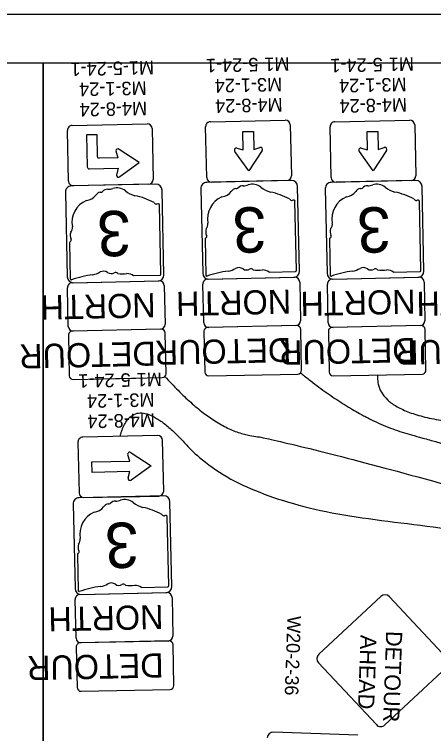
# Model space of a CAD drawing. Extents: x -15.3 to 34, y 0 to 22.
# Drawn here: x 1.2 to 5.53, y 14.57 to 22 of the extents above; entities that cross this region are included whole.
import ezdxf

# ---------------------------------------------------------------- set-up
doc = ezdxf.new("R2010")
doc.units = 0
for name, color, linetype in [('SC_Scratch1', 7, 'Continuous'), ('SH_Border', 7, 'Continuous'), ('SH_Cut_Line', 7, 'Continuous'), ('SH_Text', 7, 'Continuous'), ('SN_P_Signs', 7, 'Continuous')]:
    doc.layers.add(name, color=color, linetype=linetype)

msp = doc.modelspace()

# ---------------------------------------------------------------- linework, layer by layer
at = {"layer": 'SH_Border'}
for points in [[(0.5, 21.5), (1.5, 21.5), (1.5, 0.5), (0.5, 0.5)], [(1.5, 21.5), (33.5, 21.5), (33.5, 0.5), (1.5, 0.5)]]:
    msp.add_lwpolyline(points, close=True, dxfattribs=at)
at = {"layer": 'SH_Cut_Line'}
msp.add_lwpolyline([(0, 0), (34, 0), (34, 22), (0, 22)], close=True, dxfattribs=at)
at = {"layer": 'SH_Text'}
for points in [[(4.1592, 18.2966), (4.7515, 17.8162), (5.7312, 17.533), (8.5118, 16.773), (8.9677, 16.9331), (8.973, 16.8191)], [(2.759, 18.259), (3.2529, 17.7067), (4.0517, 17.5875), (7.8335, 16.5399), (8.7455, 16.2122), (8.9206, 16.1567), (8.973, 16.2268)], [(4.9569, 18.2744), (4.9232, 17.8865), (6.5628, 17.6894), (8.9216, 17.2583), (8.973, 17.1313)], [(2.2958, 17.6404), (2.4287, 18.163), (3.5269, 16.9468), (6.4522, 16.5976), (9.0269, 16.1255), (8.973, 15.936)]]:
    msp.add_open_spline(points, degree=2, dxfattribs=at)
at = {"layer": 'SN_P_Signs'}
for p, q in [((3.2277, 20.8905), (4.0025, 20.9071)), ((4.5133, 20.8905), (5.2881, 20.9071)), ((1.8003, 20.8524), (2.5751, 20.869)), ((2.6262, 20.82), (2.6374, 20.2952)), ((3.19, 20.3146), (3.1787, 20.8394)), ((4.0535, 20.8582), (4.0648, 20.3333)), ((4.4756, 20.3146), (4.4644, 20.8394)), ((5.3392, 20.8582), (5.3504, 20.3333)), ((1.7626, 20.2764), (1.7514, 20.8013)), ((2.0571, 20.7564), (1.9477, 20.754)), ((2.0571, 20.7564), (1.9477, 20.754)), ((1.9477, 20.754), (1.9547, 20.4259)), ((2.0619, 20.5298), (2.0571, 20.7564)), ((3.5628, 20.7883), (3.6721, 20.7907)), ((3.5668, 20.6009), (3.5628, 20.7883)), ((3.6721, 20.7907), (3.6762, 20.6032)), ((4.8484, 20.7883), (4.9578, 20.7907)), ((4.8524, 20.6009), (4.8484, 20.7883)), ((4.9578, 20.7907), (4.9618, 20.6032)), ((2.2508, 20.5885), (2.2731, 20.5188)), ((2.493, 20.4687), (2.2861, 20.6041)), ((3.5022, 20.6194), (3.5668, 20.6009)), ((3.7638, 20.5932), (3.6261, 20.3833)), ((3.6762, 20.6032), (3.7398, 20.6245)), ((4.7878, 20.6194), (4.8524, 20.6009)), ((5.0494, 20.5932), (4.9117, 20.3833)), ((4.9618, 20.6032), (5.0254, 20.6245)), ((2.2731, 20.5188), (2.0778, 20.5146)), ((3.6261, 20.3833), (3.482, 20.5843)), ((4.9117, 20.3833), (4.7676, 20.5843)), ((2.292, 20.3246), (2.493, 20.4687)), ((1.9786, 20.403), (2.2755, 20.4094)), ((1.9786, 20.403), (1.9786, 20.403)), ((2.2755, 20.4094), (2.2562, 20.3386)), ((2.5885, 20.2441), (1.8137, 20.2275)), ((4.0159, 20.2822), (3.241, 20.2656)), ((5.3015, 20.2822), (4.5267, 20.2656)), ((4.1176, 19.3563), (4.1024, 20.0676)), ((5.4033, 19.3563), (5.388, 20.0676)), ((2.7174, 19.3187), (2.7022, 20.0301)), ((1.7729, 19.6409), (1.7808, 19.2688)), ((1.7729, 19.6408), (1.7729, 19.6409)), ((3.1731, 19.6785), (3.181, 19.3063)), ((3.1731, 19.6784), (3.1731, 19.6785)), ((4.4587, 19.6785), (4.4666, 19.3063)), ((4.4588, 19.6784), (4.4587, 19.6785)), ((3.8342, 19.3379), (4.1087, 19.3438)), ((5.1198, 19.3379), (5.3943, 19.3438)), ((2.434, 19.3004), (2.7085, 19.3063)), ((3.2, 19.2645), (4.0997, 19.2838)), ((4.4856, 19.2645), (5.3854, 19.2838)), ((1.7594, 18.776), (1.7508, 19.1759)), ((1.7998, 19.227), (2.6995, 19.2463)), ((2.7506, 19.1973), (2.7592, 18.7974)), ((3.1596, 18.8136), (3.151, 19.2135)), ((4.1508, 19.2349), (4.1594, 18.835)), ((4.4452, 18.8136), (4.4367, 19.2135)), ((5.4364, 19.2349), (5.445, 18.835)), ((2.7102, 18.7464), (1.8105, 18.7271)), ((4.1104, 18.7839), (3.2107, 18.7646)), ((5.3961, 18.7839), (4.4963, 18.7646)), ((2.6832, 17.6487), (1.9083, 17.6321)), ((1.8594, 17.581), (1.8707, 17.0561)), ((2.7455, 17.0749), (2.7342, 17.5997)), ((2.4079, 17.47), (2.6149, 17.3346)), ((2.395, 17.3847), (2.3737, 17.4483)), ((2.0045, 17.3763), (2.395, 17.3847)), ((2.0068, 17.2669), (2.0045, 17.3763)), ((2.6149, 17.3346), (2.411, 17.1881)), ((2.3973, 17.2753), (2.0068, 17.2669)), ((2.3788, 17.2107), (2.3973, 17.2753)), ((1.9217, 17.0072), (2.6965, 17.0238)), ((1.9216, 17.0072), (1.9217, 17.0072)), ((2.7983, 16.0978), (2.7831, 16.8092)), ((1.8537, 16.42), (1.8617, 16.0479)), ((1.8538, 16.4199), (1.8537, 16.42)), ((2.5149, 16.0795), (2.7894, 16.0854)), ((1.8806, 16.0061), (2.7804, 16.0254)), ((1.8403, 15.5551), (1.8317, 15.9551)), ((2.8315, 15.9765), (2.84, 15.5765)), ((2.7911, 15.5255), (1.8913, 15.5062))]:
    msp.add_line(p, q, dxfattribs=at)
for points in [[(2.6656, 20.2458), (1.7908, 20.227)], [(4.0658, 20.2833), (3.191, 20.2646)], [(4.1484, 19.3473), (4.1297, 20.2221)], [(5.3515, 20.2833), (4.4767, 20.2646)], [(5.434, 19.3473), (5.4153, 20.2221)], [(1.7297, 20.1632), (1.7484, 19.2884)], [(2.7482, 19.3098), (2.7295, 20.1846)], [(3.1299, 20.2007), (3.1486, 19.3259)], [(4.4155, 20.2007), (4.4342, 19.3259)], [(3.2124, 19.2648), (4.0872, 19.2835)], [(4.4981, 19.2648), (5.3729, 19.2835)], [(1.8122, 19.2273), (2.687, 19.246)], [(2.7202, 18.7466), (1.8005, 18.7269)], [(4.1204, 18.7841), (3.2007, 18.7644)], [(4.1703, 18.3251), (4.1613, 18.745)], [(5.4061, 18.7841), (4.4863, 18.7644)], [(5.4559, 18.3251), (5.4469, 18.745)], [(1.7613, 18.686), (1.7703, 18.2661)], [(2.7701, 18.2875), (2.7611, 18.7074)], [(3.1615, 18.7236), (3.1705, 18.3037)], [(4.4471, 18.7236), (4.4561, 18.3037)], [(3.2114, 18.2645), (4.1311, 18.2842)], [(4.497, 18.2645), (5.4168, 18.2842)], [(1.8112, 18.227), (2.7309, 18.2467)], [(2.7465, 17.0249), (1.8717, 17.0061)], [(2.8291, 16.0889), (2.8104, 16.9637)], [(1.8106, 16.9423), (1.8293, 16.0675)], [(1.8931, 16.0064), (2.7679, 16.0251)], [(4.3492, 15.3894), (4.989, 15.9863)], [(5.0773, 15.9832), (5.6742, 15.3434)], [(1.8422, 15.4652), (1.8512, 15.0453)], [(2.8011, 15.5257), (1.8813, 15.506)], [(2.851, 15.0667), (2.842, 15.4866)], [(4.943, 14.6613), (4.3461, 15.3011)], [(5.6712, 15.2551), (5.0313, 14.6582)], [(1.892, 15.0061), (2.8118, 15.0258)], [(4.7535, 14.5544), (3.879, 14.5848)]]:
    msp.add_lwpolyline(points, dxfattribs=at)
for centre, radius, start, end in [((3.2287, 20.8405), 0.05, 91.22636, 181.22636), ((4.0036, 20.8571), 0.05, 1.22636, 91.22636), ((4.5143, 20.8405), 0.05, 91.22636, 181.22636), ((5.2892, 20.8571), 0.05, 1.22636, 91.22636), ((1.8014, 20.8024), 0.05, 91.22636, 181.22636), ((2.5762, 20.819), 0.05, 1.22636, 91.22636), ((2.2716, 20.589), 0.0208, 46.2265, 181.22802), ((3.4965, 20.5993), 0.0209, 74.02176, 226.23592), ((3.7464, 20.6047), 0.0209, 326.63758, 108.43097), ((4.7821, 20.5993), 0.0209, 74.02176, 226.23592), ((5.032, 20.6047), 0.0209, 326.63758, 108.43097), ((2.0775, 20.5302), 0.0156, 181.22636, 271.22636), ((1.9782, 20.4264), 0.0234, 181.22636, 271.22636), ((2.277, 20.339), 0.0208, 181.22802, 316.22622), ((2.5874, 20.2941), 0.05, 271.22636, 1.22636), ((3.24, 20.3156), 0.05, 181.22636, 271.22636), ((4.0148, 20.3322), 0.05, 271.22636, 1.22636), ((4.5256, 20.3156), 0.05, 181.22636, 271.22636), ((5.3004, 20.3322), 0.05, 271.22636, 1.22636), ((1.7922, 20.1645), 0.0625, 91.22636, 181.22636), ((1.8126, 20.2775), 0.05, 181.22636, 271.22636), ((2.667, 20.1833), 0.0625, 1.22636, 91.22636), ((3.1924, 20.2021), 0.0625, 91.22636, 181.22636), ((3.5685, 20.1541), 0.0759, 90.00338, 136.77564), ((3.5748, 20.347), 0.1171, 266.92149, 292.43631), ((3.6624, 20.1028), 0.1425, 51.92674, 107.5182), ((3.8994, 20.383), 0.2246, 228.41052, 257.06234), ((4.0672, 20.2208), 0.0625, 1.22636, 91.22636), ((4.478, 20.2021), 0.0625, 91.22636, 181.22636), ((4.8541, 20.1541), 0.0759, 90.00338, 136.77564), ((4.8604, 20.347), 0.1171, 266.92149, 292.43631), ((4.948, 20.1028), 0.1425, 51.92674, 107.5182), ((5.185, 20.383), 0.2246, 228.41052, 257.06234), ((5.3528, 20.2208), 0.0625, 1.22636, 91.22636), ((2.1094, 20.0864), 0.0803, 104.09955, 144.50347), ((2.0981, 20.184), 0.0214, 246.97809, 313.87479), ((2.1683, 20.1166), 0.0759, 90.00338, 136.77564), ((2.1746, 20.3095), 0.1171, 266.92149, 292.43631), ((2.2622, 20.0653), 0.1425, 51.92674, 107.5182), ((2.4992, 20.3455), 0.2246, 228.41052, 257.06234), ((3.3342, 20.251), 0.1362, 275.62949, 323.80311), ((3.5096, 20.1239), 0.0803, 104.09955, 144.50347), ((3.4983, 20.2215), 0.0214, 246.97809, 313.87479), ((3.7051, 19.4608), 0.7179, 61.63929, 78.42486), ((4.6199, 20.251), 0.1362, 275.62949, 323.80311), ((4.7952, 20.1239), 0.0803, 104.09955, 144.50347), ((4.784, 20.2215), 0.0214, 246.97809, 313.87479), ((4.9907, 19.4608), 0.7179, 61.63929, 78.42486), ((2.0467, 19.8499), 0.2487, 113.53525, 190.2122), ((1.934, 20.2135), 0.1362, 275.62949, 323.80311), ((2.3049, 19.4232), 0.7179, 61.63929, 78.42486), ((3.4469, 19.8875), 0.2487, 113.53525, 190.2122), ((4.0719, 20.108), 0.0302, 210.97474, 274.49811), ((4.0914, 19.9961), 0.0836, 88.56536, 101.83022), ((4.0916, 20.069), 0.011, 353.18475, 79.53298), ((4.7325, 19.8875), 0.2487, 113.53525, 190.2122), ((5.3576, 20.108), 0.0302, 210.97474, 274.49811), ((5.3771, 19.9961), 0.0836, 88.56536, 101.83022), ((5.3772, 20.069), 0.011, 353.18475, 79.53298), ((2.6717, 20.0705), 0.0302, 210.97474, 274.49811), ((2.6913, 19.9586), 0.0836, 88.56536, 101.83022), ((2.6914, 20.0314), 0.011, 353.18475, 79.53298), ((3.1323, 19.8334), 0.0705, 318.03286, 8.15596), ((4.418, 19.8334), 0.0705, 318.03286, 8.15596), ((1.7321, 19.7958), 0.0705, 318.03286, 8.15596), ((3.2766, 19.7551), 0.097, 161.25933, 204.87593), ((4.5622, 19.7551), 0.097, 161.25933, 204.87593), ((1.8764, 19.7175), 0.097, 161.25933, 204.87593), ((3.1749, 19.7058), 0.0162, 289.17035, 31.56333), ((4.4605, 19.7058), 0.0162, 289.17035, 31.56333), ((1.784, 19.6426), 0.0112, 110.83017, 188.96049), ((1.7747, 19.6683), 0.0162, 289.17035, 31.56333), ((3.1842, 19.6801), 0.0112, 110.83017, 188.96049), ((4.4698, 19.6801), 0.0112, 110.83017, 188.96049), ((1.9829, 19.5081), 0.2, 278.57254, 301.99522), ((2.1222, 19.2702), 0.076, 55.08257, 116.05455), ((2.2014, 19.3847), 0.0632, 235.69305, 300.36749), ((2.2477, 19.3035), 0.0304, 41.01842, 118.32873), ((2.3252, 19.6976), 0.3782, 261.71305, 276.21463), ((2.3704, 19.2164), 0.1053, 52.84587, 92.33825), ((3.2111, 19.3273), 0.0625, 181.22636, 271.22636), ((3.5353, 18.3613), 0.9942, 97.07083, 110.13282), ((3.3831, 19.5457), 0.2, 278.57254, 301.99522), ((3.5224, 19.3077), 0.076, 55.08257, 116.05455), ((3.6016, 19.4223), 0.0632, 235.69305, 300.36749), ((3.6479, 19.341), 0.0304, 41.01842, 118.32873), ((3.7254, 19.7352), 0.3782, 261.71305, 276.21463), ((3.7706, 19.254), 0.1053, 52.84587, 92.33825), ((4.0859, 19.346), 0.0625, 271.22636, 1.22636), ((4.1069, 19.3545), 0.0109, 279.35647, 9.35647), ((4.4967, 19.3273), 0.0625, 181.22636, 271.22636), ((4.8209, 18.3613), 0.9942, 97.07083, 110.13282), ((4.6687, 19.5457), 0.2, 278.57254, 301.99522), ((4.8081, 19.3077), 0.076, 55.08257, 116.05455), ((4.8872, 19.4223), 0.0632, 235.69305, 300.36749), ((4.9335, 19.341), 0.0304, 41.01842, 118.32873), ((5.011, 19.7352), 0.3782, 261.71305, 276.21463), ((5.0562, 19.254), 0.1053, 52.84587, 92.33825), ((5.3715, 19.346), 0.0625, 271.22636, 1.22636), ((5.3926, 19.3545), 0.0109, 279.35647, 9.35647), ((1.8109, 19.2897), 0.0625, 181.22636, 271.22636), ((1.7913, 19.2675), 0.0104, 173.08845, 278.96436), ((2.1351, 18.3237), 0.9942, 97.07083, 110.13282), ((2.6857, 19.3085), 0.0625, 271.22636, 1.22636), ((2.7067, 19.317), 0.0109, 279.35647, 9.35647), ((3.201, 19.2146), 0.05, 91.22636, 181.22636), ((3.1915, 19.305), 0.0104, 173.08845, 278.96436), ((4.1008, 19.2338), 0.05, 1.22636, 91.22636), ((4.4867, 19.2146), 0.05, 91.22636, 181.22636), ((4.4771, 19.305), 0.0104, 173.08845, 278.96436), ((5.3865, 19.2338), 0.05, 1.22636, 91.22636), ((1.8008, 19.177), 0.05, 91.22636, 181.22636), ((2.7006, 19.1963), 0.05, 1.22636, 91.22636), ((3.2096, 18.8147), 0.05, 181.22636, 271.22636), ((4.1094, 18.8339), 0.05, 271.22636, 1.22636), ((4.4952, 18.8147), 0.05, 181.22636, 271.22636), ((5.395, 18.8339), 0.05, 271.22636, 1.22636), ((1.8094, 18.7771), 0.05, 181.22636, 271.22636), ((1.8013, 18.6869), 0.04, 91.22636, 181.22636), ((2.7092, 18.7964), 0.05, 271.22636, 1.22636), ((2.7211, 18.7066), 0.04, 1.22636, 91.22636), ((3.2015, 18.7244), 0.04, 91.22636, 181.22636), ((4.1213, 18.7441), 0.04, 1.22636, 91.22636), ((4.4871, 18.7244), 0.04, 91.22636, 181.22636), ((5.4069, 18.7441), 0.04, 1.22636, 91.22636), ((2.7301, 18.2867), 0.04, 271.22636, 1.22636), ((3.2105, 18.3045), 0.04, 181.22636, 271.22636), ((4.1303, 18.3242), 0.04, 271.22636, 1.22636), ((4.4961, 18.3045), 0.04, 181.22636, 271.22636), ((5.4159, 18.3242), 0.04, 271.22636, 1.22636), ((1.8103, 18.267), 0.04, 181.22636, 271.22636), ((1.9094, 17.5821), 0.05, 91.22636, 181.22636), ((2.6842, 17.5987), 0.05, 1.22636, 91.22636), ((2.3934, 17.4549), 0.0209, 46.21681, 198.43097), ((2.3988, 17.205), 0.0209, 164.02176, 305.81514), ((1.9206, 17.0572), 0.05, 181.22636, 271.22636), ((2.6954, 17.0738), 0.05, 271.22636, 1.22636), ((2.7479, 16.9624), 0.0625, 1.22636, 91.22636), ((1.8731, 16.9437), 0.0625, 91.22636, 181.22636), ((2.1902, 16.8655), 0.0803, 104.09955, 144.50347), ((2.179, 16.9631), 0.0214, 246.97809, 313.87479), ((2.2492, 16.8957), 0.0759, 90.00338, 136.77564), ((2.2555, 17.0886), 0.1171, 266.92149, 292.43631), ((2.3431, 16.8444), 0.1425, 51.92674, 107.5182), ((2.5801, 17.1246), 0.2246, 228.41052, 257.06234), ((2.0149, 16.9926), 0.1362, 275.62949, 323.80311), ((2.3857, 16.2023), 0.7179, 61.63929, 78.42486), ((2.1276, 16.6291), 0.2487, 113.53525, 190.2122), ((2.7526, 16.8496), 0.0302, 210.97474, 274.49811), ((2.7721, 16.7377), 0.0836, 88.56536, 101.83022), ((2.7722, 16.8105), 0.011, 353.18475, 79.53298), ((1.813, 16.575), 0.0705, 318.03286, 8.15596), ((1.9573, 16.4966), 0.097, 161.25933, 204.87593), ((1.8648, 16.4217), 0.0112, 110.83017, 188.96049), ((1.8556, 16.4474), 0.0162, 289.17035, 31.56333), ((1.8918, 16.0689), 0.0625, 181.22636, 271.22636), ((2.216, 15.1028), 0.9942, 97.07083, 110.13282), ((2.0638, 16.2872), 0.2, 278.57254, 301.99522), ((2.2031, 16.0493), 0.076, 55.08257, 116.05455), ((2.2822, 16.1638), 0.0632, 235.69305, 300.36749), ((2.3286, 16.0826), 0.0304, 41.01842, 118.32873), ((2.406, 16.4768), 0.3782, 261.71305, 276.21463), ((2.4513, 15.9955), 0.1053, 52.84587, 92.33825), ((2.7666, 16.0876), 0.0625, 271.22636, 1.22636), ((2.7876, 16.0961), 0.0109, 279.35647, 9.35647), ((1.8817, 15.9561), 0.05, 91.22636, 181.22636), ((1.8721, 16.0466), 0.0104, 173.08845, 278.96436), ((2.7815, 15.9754), 0.05, 1.22636, 91.22636), ((5.0316, 15.9406), 0.0625, 43.0119, 133.0119), ((1.8903, 15.5562), 0.05, 181.22636, 271.22636), ((2.7901, 15.5755), 0.05, 271.22636, 1.22636), ((1.8822, 15.466), 0.04, 91.22636, 181.22636), ((2.802, 15.4857), 0.04, 1.22636, 91.22636), ((4.3918, 15.3437), 0.0625, 133.0119, 223.0119), ((1.8912, 15.0461), 0.04, 181.22636, 271.22636), ((2.811, 15.0658), 0.04, 271.22636, 1.22636), ((4.9887, 14.7039), 0.0625, 223.0119, 313.0119), ((3.8768, 14.5223), 0.0625, 88.0119, 178.0119)]:
    msp.add_arc(centre, radius, start, end, dxfattribs=at)

# ---------------------------------------------------------------- texts
at = {"layer": 'SC_Scratch1'}
for s, rotation, p in [('M1-5-24-1', 181.22636, (4.0445, 21.5582)), ('M1-5-24-1', 181.22636, (5.3301, 21.5582)), ('M1-5-24-1', 181.22636, (2.6443, 21.5207)), ('M3-1-24', 181.22636, (3.9684, 21.3466)), ('M3-1-24', 181.22636, (5.254, 21.3466)), ('M3-1-24', 181.22636, (2.5682, 21.309)), ('M4-8-24', 181.22636, (3.9729, 21.1366)), ('M4-8-24', 181.22636, (5.2585, 21.1366)), ('M4-8-24', 181.22636, (2.5727, 21.0991)), ('M1-5-24-1', 181.22636, (2.7252, 18.2998)), ('M3-1-24', 181.22636, (2.6491, 18.0881)), ('M4-8-24', 181.22636, (2.6536, 17.8782)), ('W20-2-36', 268.0119, (4.0245, 15.7871))]:
    msp.add_text(s, height=0.14, rotation=rotation, dxfattribs=at).set_placement(p)
at = {"layer": 'SN_P_Signs'}
for s, height, rotation, p in [('3', 0.4688, 181.22636, (3.8013, 20.011)), ('3', 0.4688, 181.22636, (5.0869, 20.011)), ('3', 0.4688, 181.22636, (2.4011, 19.9735)), ('NORTH', 0.25, 181.22636, (2.6589, 19.1204)), ('NORTH', 0.25, 181.22636, (4.0591, 19.1579)), ('NORTH', 0.25, 181.22636, (5.3447, 19.1579)), ('NORTH', 0.25, 181.22636, (6.5431, 19.1579)), ('DETOUR', 0.25, 181.22636, (4.0615, 18.6578)), ('DETOUR', 0.25, 181.22636, (5.3471, 18.6578)), ('DETOUR', 0.25, 181.22636, (6.5456, 18.6578)), ('DETOUR', 0.25, 181.22636, (2.6613, 18.6203)), ('3', 0.4688, 181.22636, (2.482, 16.7526)), ('NORTH', 0.25, 181.22636, (2.7398, 15.8995)), ('DETOUR', 0.16667, 268.0119, (5.0452, 15.6311)), ('AHEAD', 0.16667, 268.0119, (4.7798, 15.5903)), ('DETOUR', 0.25, 181.22636, (2.7422, 15.3994))]:
    msp.add_text(s, height=height, rotation=rotation, dxfattribs=at).set_placement(p)

doc.saveas('drawing.dxf')
